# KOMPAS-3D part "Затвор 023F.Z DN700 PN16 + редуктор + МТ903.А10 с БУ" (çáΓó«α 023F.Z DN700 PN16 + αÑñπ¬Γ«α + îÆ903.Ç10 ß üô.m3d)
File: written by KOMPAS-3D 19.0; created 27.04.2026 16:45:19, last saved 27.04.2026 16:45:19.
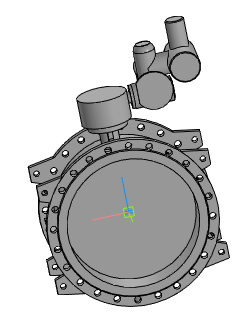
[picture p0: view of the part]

Document properties: Полное имя файла: ..\..\Затвор 023F.Z DN400-DN1600 + редуктор + МТ903\Затвор 023F.Z DN700 PN16 + редуктор + МТ903.А10 с БУ.a3d

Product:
- Part/product: Затвор 023F.Z DN700 PN16 + редуктор + МТ903.А10 с БУ
    Масса: 719.544

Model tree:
1. Операция без истории:1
